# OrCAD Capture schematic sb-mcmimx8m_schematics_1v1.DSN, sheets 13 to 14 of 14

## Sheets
13 12. ALT boot: size C; title: SBC-MCM-iMX8M    12.ALT-BOOT; rev: 2.0
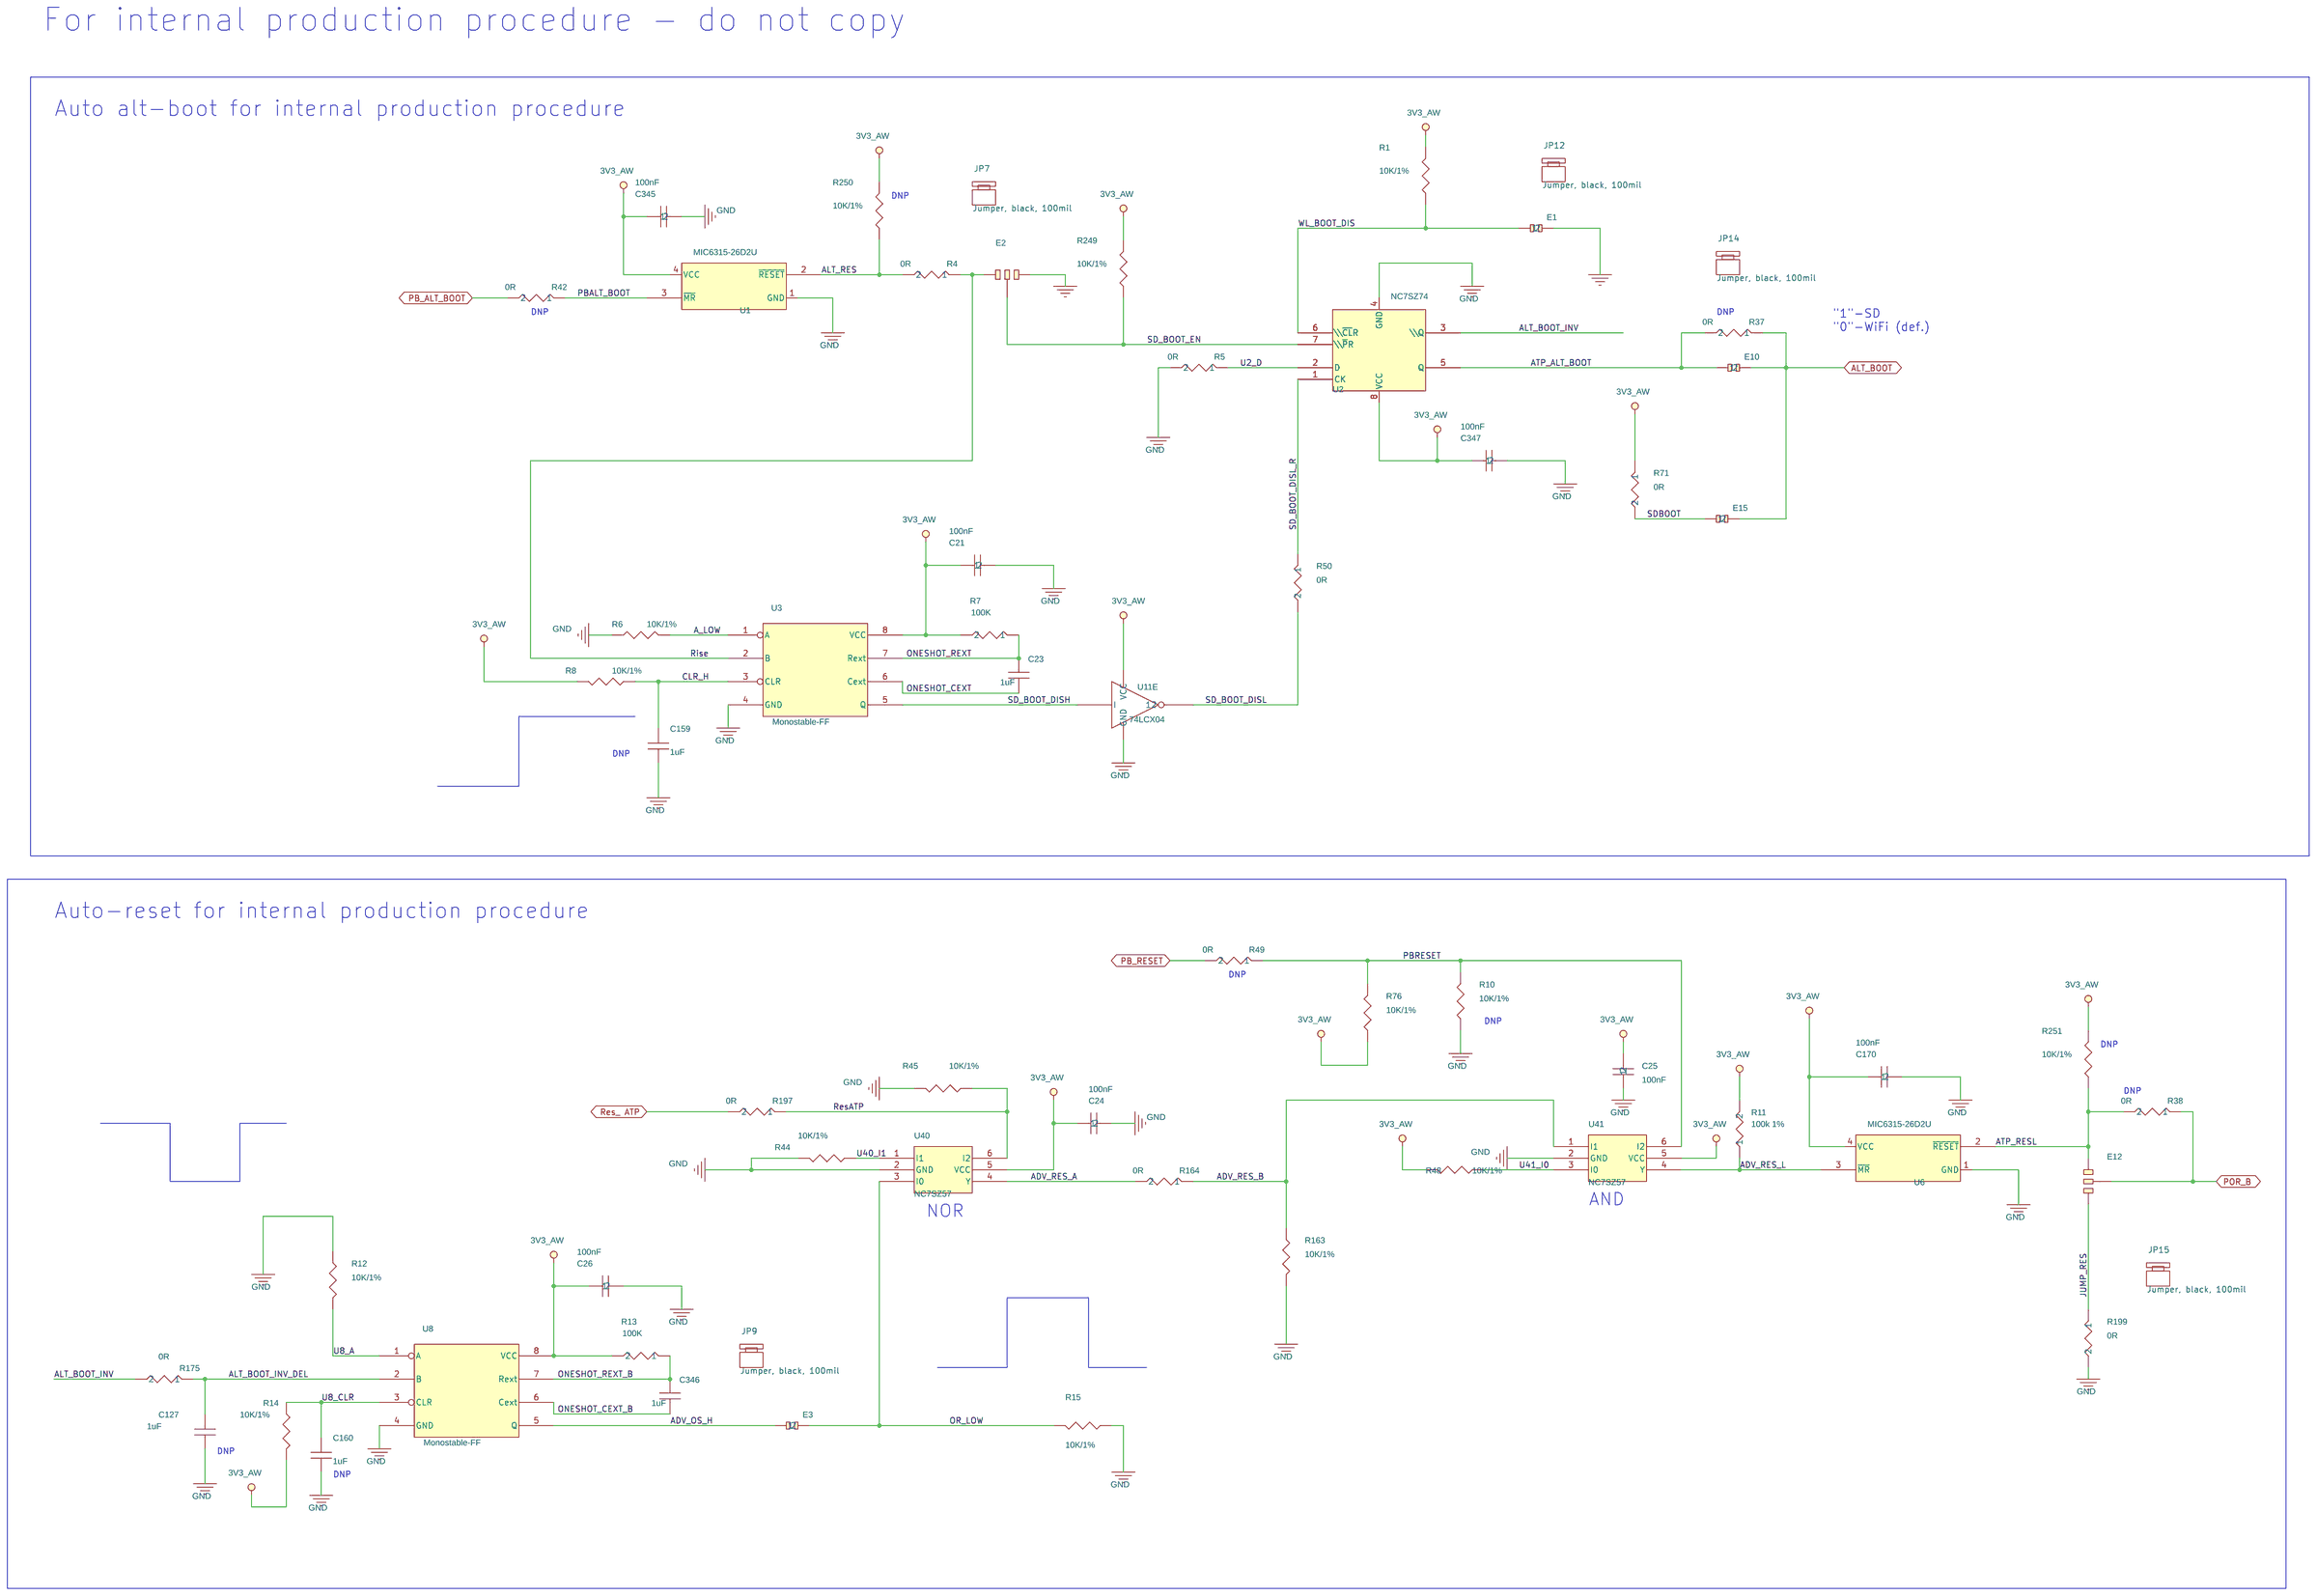
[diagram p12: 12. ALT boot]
14 14. Mechanical,MISC connectors: size B; title: SBC-MCM-iMX8M      11. Mechanical; rev: 2.0
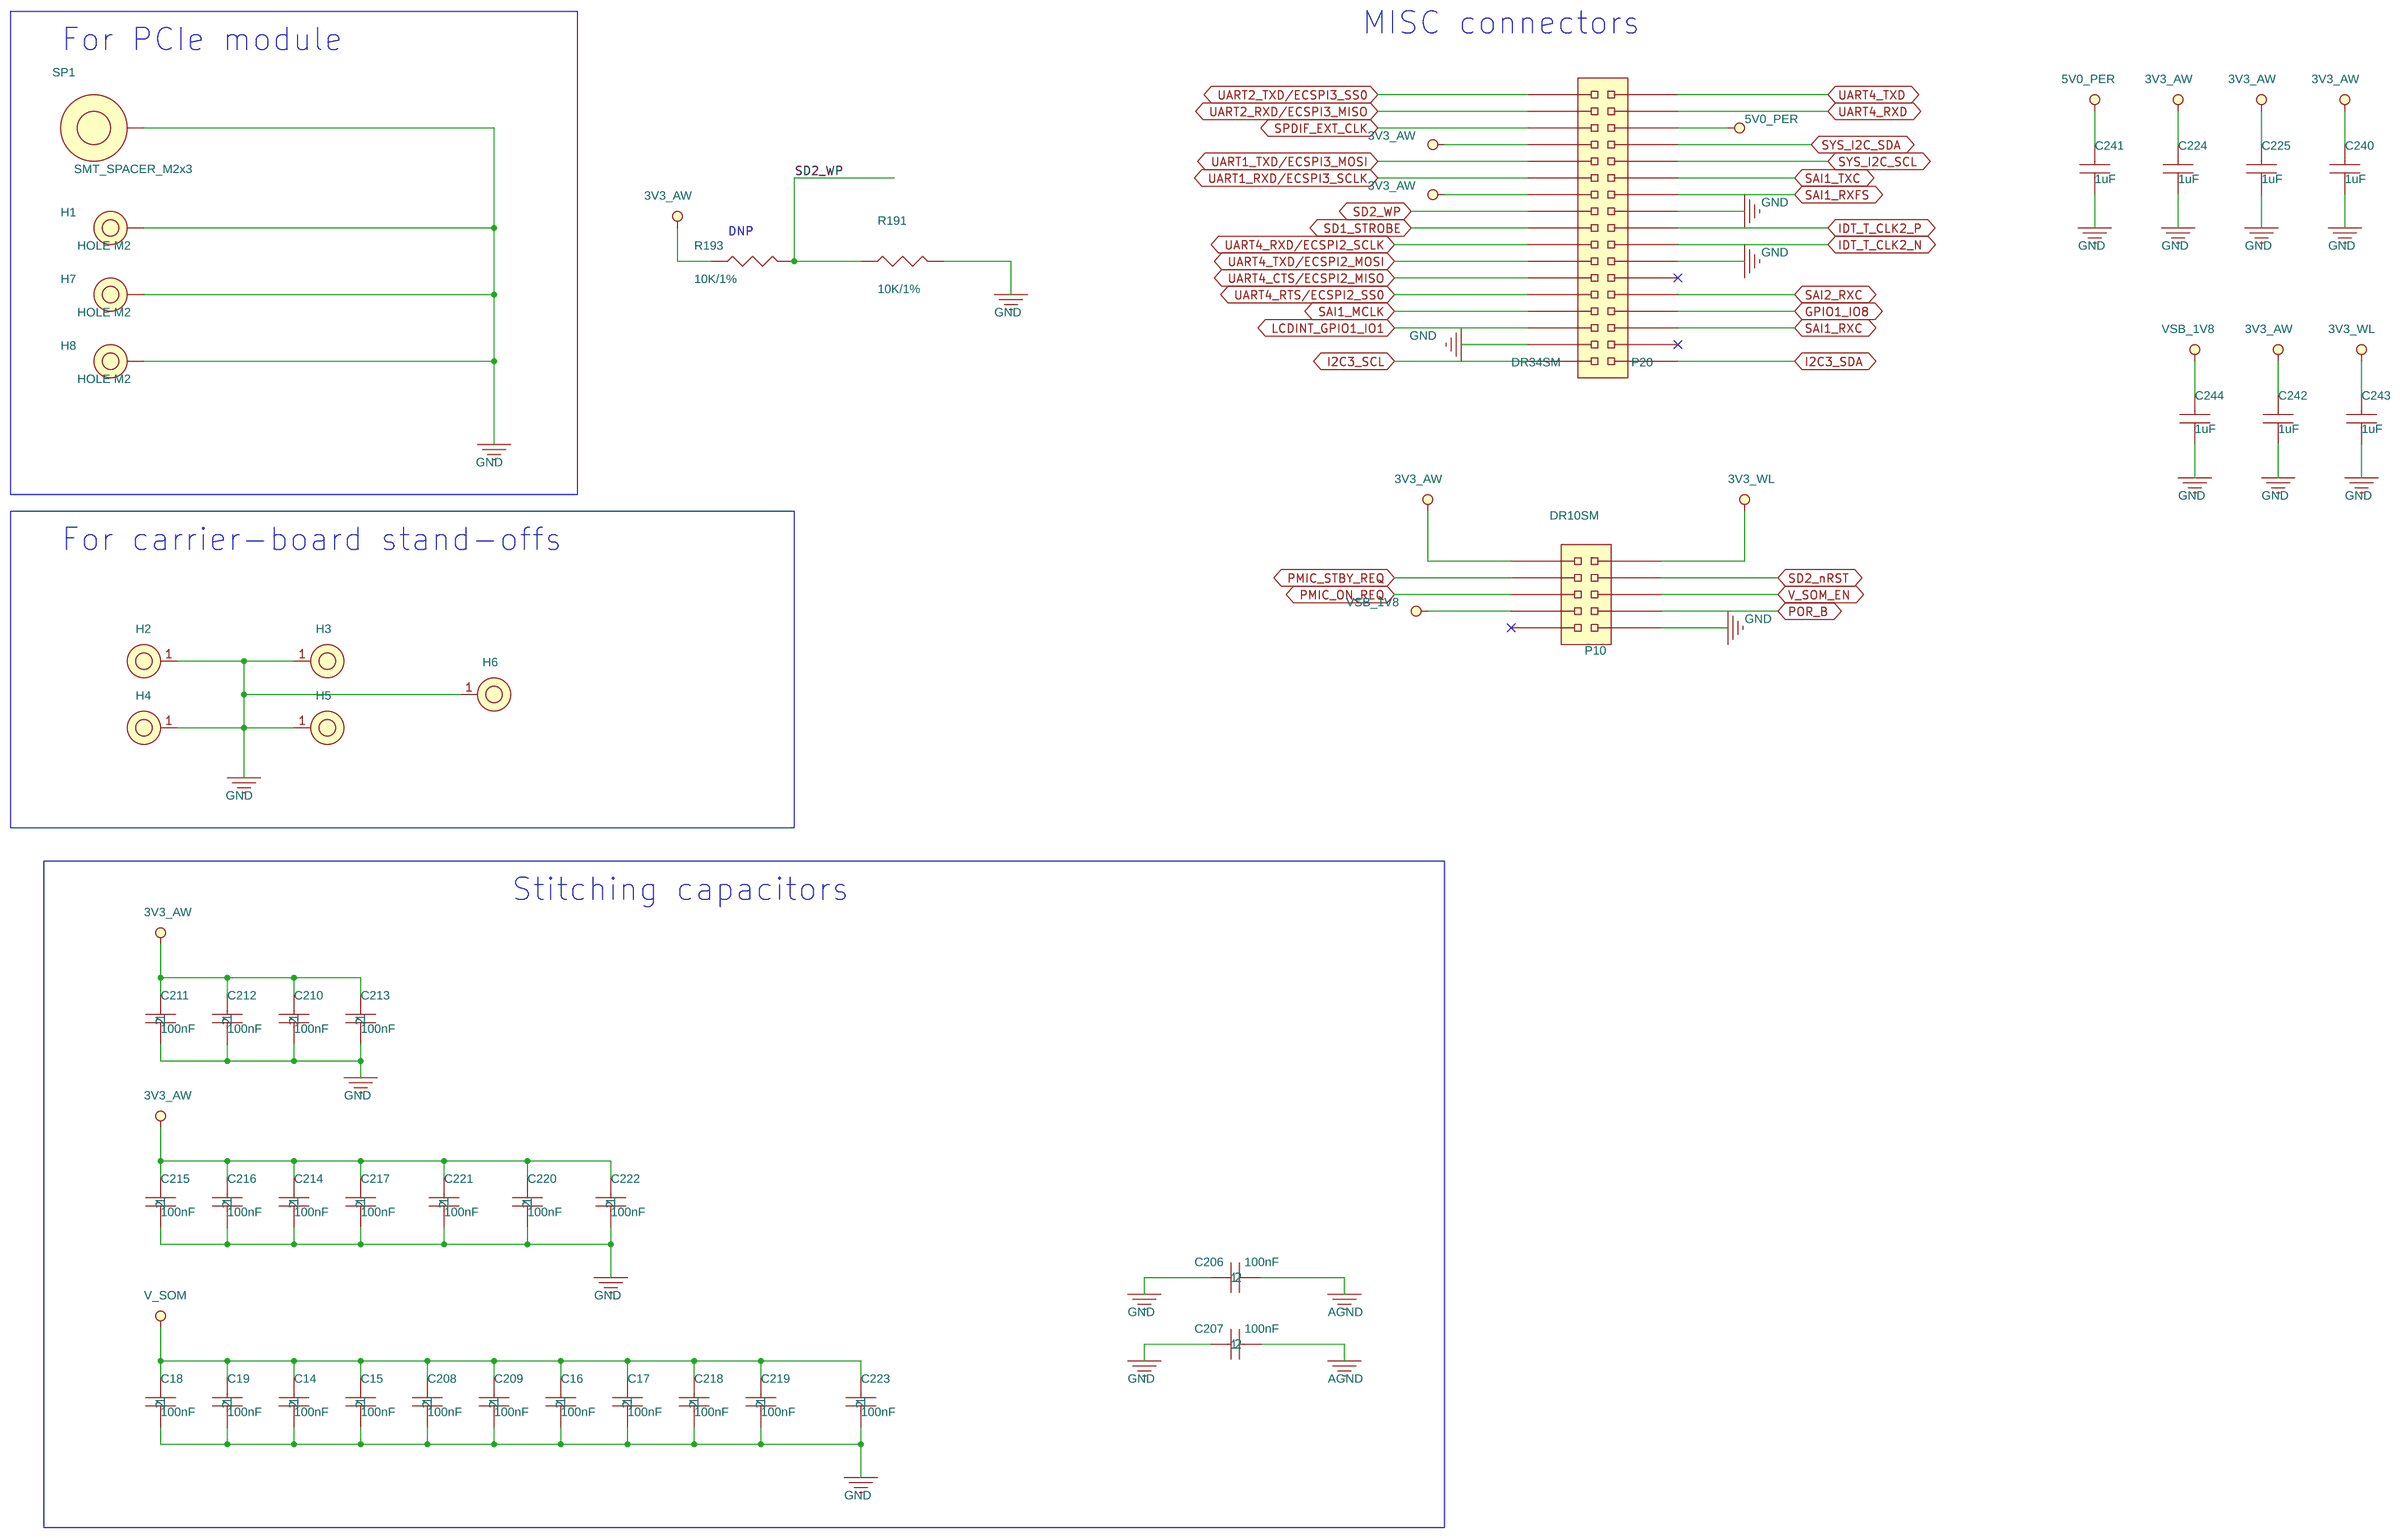
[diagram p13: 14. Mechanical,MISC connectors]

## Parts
sheet 10. UART, RS232, SD, EPROM,QSPI
U11  74LCX04  [TSSOP-14]  (sections A,B,C,D,E,F)
sheet 12. ALT boot
C21  100nF  [RC0402]
C23  1uF  [RC0402]
C24  100nF  [RC0402]
C25  100nF  [RC0402]
C26  100nF  [RC0402]
C127  1uF  [RC0402]
C159  1uF  [RC0402]
C160  1uF  [RC0402]
C170  100nF  [RC0402]
C345  100nF  [RC0402]
C346  1uF  [RC0402]
C347  100nF  [RC0402]
E1  HDR1X2  [1X2THHDR]
E2  JP3  [1X3THHDR]
E3  HDR1X2  [1X2THHDR]
E10  HDR1X2  [1X2THHDR]
E12  JP3  [1X3THHDR]
E15  HDR1X2  [1X2THHDR]
JP7  Jumper, black, 100mil
JP9  Jumper, black, 100mil
JP12  Jumper, black, 100mil
JP14  Jumper, black, 100mil
JP15  Jumper, black, 100mil
R1  10K/1%  [RC0402]
R4  0R  [RC0402]
R5  0R  [RC0402]
R6  10K/1%  [RC0402]
R7  100K  [RC0402]
R8  10K/1%  [RC0402]
R10  10K/1%  [RC0402]
R11  100k 1%  [RC0402]
R12  10K/1%  [RC0402]
R13  100K  [RC0402]
R14  10K/1%  [RC0402]
R15  10K/1%  [RC0402]
R37  0R  [RC0402]
R38  0R  [RC0402]
R42  0R  [RC0402]
R44  10K/1%  [RC0402]
R45  10K/1%  [RC0402]
R48  10K/1%  [RC0402]
R49  0R  [RC0402]
R50  0R  [RC0402]
R71  0R  [RC0402]
R76  10K/1%  [RC0402]
R163  10K/1%  [RC0402]
R164  0R  [RC0402]
R175  0R  [RC0402]
R197  0R  [RC0402]
R199  0R  [RC0402]
R249  10K/1%  [RC0402]
R250  10K/1%  [RC0402]
R251  10K/1%  [RC0402]
U1  MIC6315-26D2U  [SOT-143]
U2  NC7SZ74  [MO-187CA-8]
U3  Monostable-FF  [MO-187CA-8]
U6  MIC6315-26D2U  [SOT-143]
U8  Monostable-FF  [MO-187CA-8]
U40  NC7SZ57  [MO-252UAAD]
U41  NC7SZ57  [MO-252UAAD]
sheet 14. Mechanical,MISC connectors
C14  100nF  [RC0402]
C15  100nF  [RC0402]
C16  100nF  [RC0402]
C17  100nF  [RC0402]
C18  100nF  [RC0402]
C19  100nF  [RC0402]
C206  100nF  [RC0402]
C207  100nF  [RC0402]
C208  100nF  [RC0402]
C209  100nF  [RC0402]
C210  100nF  [RC0402]
C211  100nF  [RC0402]
C212  100nF  [RC0402]
C213  100nF  [RC0402]
C214  100nF  [RC0402]
C215  100nF  [RC0402]
C216  100nF  [RC0402]
C217  100nF  [RC0402]
C218  100nF  [RC0402]
C219  100nF  [RC0402]
C220  100nF  [RC0402]
C221  100nF  [RC0402]
C222  100nF  [RC0402]
C223  100nF  [RC0402]
C224  1uF  [RC0402]
C225  1uF  [RC0402]
C240  1uF  [RC0402]
C241  1uF  [RC0402]
C242  1uF  [RC0402]
C243  1uF  [RC0402]
C244  1uF  [RC0402]
H1  HOLE M2  [M2PAD]
H2  MechHole  [M3PAD]
H3  MechHole  [M3PAD]
H4  MechHole  [M3PAD]
H5  MechHole  [M3PAD]
H6  MechHole  [M3PAD]
H7  HOLE M2  [M2PAD]
H8  HOLE M2  [M2PAD]
P10  DR10SM  [2X5SMHDR]
P20  DR34SM  [2X17SMHDR]
R191  10K/1%  [RC0402]
R193  10K/1%  [RC0402]
SP1  SMT_SPACER_M2x3  [MINIPCIE-4-Spacer]

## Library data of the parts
U11 = 74LCX04_sgl_gate_TSSOP-14: CLABCONF0: =SB-MCM8M
C21 = 100nF,_10V,_X7R,_10%,_0402_4: CLABCONF0: =ATP
C23 C346 = 1uF,X5R,6.3V,0402: CLABCONF0: =ATP
C24 = 100nF,_10V,_X7R,_10%,_0402_6: CLABCONF0: =ATP
C25 = 100nF,_10V,_X7R,_10%,_0402_2: CLABCONF0: =ATP
C26 = 100nF,_10V,_X7R,_10%,_0402_1: CLABCONF0: =ATP
C127 C159 C160 = 1uF,X5R,6.3V,0402: CLABCONF0: DNP
C170 = 100nF,_10V,_X7R,_10%,_0402_5: CLABCONF0: =ATP
C345 = 100nF,_10V,_X7R,_10%,_0402_3: CLABCONF0: =ATP
C347 = 100nF,_10V,_X7R,_10%,_0402: CLABCONF0: =ATP
E1 = HDR_1x2_100MIL_TH_JUMPER_3: CLABCONF0: =ATP
E2 E12 = HDR_1x3_100MIL_TH_JUMPER: CLABCONF0: =ATP
E3 = HDR_1x2_100MIL_TH_JUMPER_1: CLABCONF0: =ATP
E10 = HDR_1x2_100MIL_TH_JUMPER_2: CLABCONF0: =ATP
E15 = HDR_1x2_100MIL_TH_JUMPER: CLABCONF0: =SB-MCM8M
JP7 JP9 JP12 JP14 JP15 = Jumper,_black,_100mil: CLABCONF0: =ATP
R1 = 10K,1%,0402,1_16W_0_9: CLABCONF0: =ATP
R4 = 0R,_0402_0_5: CLABCONF0: =ATP; P/N: 161C00005S
R5 = 0R,_0402_0_7: CLABCONF0: =ATP; P/N: 161C00005S
R6 = 10K,1%,0402,1_16W_0_1: CLABCONF0: =ATP
R7 = 100K,_0402_1: CLABCONF0: =ATP; P/N: 161C10031S
R8 = 10K,1%,0402,1_16W_0_13: CLABCONF0: =ATP
R10 = 10K,1%,0402,1_16W_0_4: CLABCONF0: DNP
R11 = 100k,_%1,_0402: CLABCONF0: =ATP
R12 = 10K,1%,0402,1_16W_0_2: CLABCONF0: =ATP
R13 = 100K,_0402: CLABCONF0: =ATP; P/N: 161C10031S
R14 = 10K,1%,0402,1_16W_0_14: CLABCONF0: =ATP
R15 = 10K,1%,0402,1_16W_0_7: CLABCONF0: =ATP
R37 = 0R,_0402_0_11: CLABCONF0: DNP; P/N: 161C00005S
R38 = 0R,_0402_0: CLABCONF0: DNP; P/N: 161C00005S
R42 = 0R,_0402_0_3: CLABCONF0: DNP; P/N: 161C00005S
R44 = 10K,1%,0402,1_16W_0_6: CLABCONF0: =ATP
R45 = 10K,1%,0402,1_16W_0_3: CLABCONF0: =ATP
R48 = 10K,1%,0402,1_16W_0_12: CLABCONF0: =ATP
R49 = 0R,_0402_0_8: CLABCONF0: DNP; P/N: 161C00005S
R50 = 0R,_0402_0_6: CLABCONF0: =ATP; P/N: 161C00005S
R71 = 0R,_0402_0_4: CLABCONF0: =SB-MCM8M; P/N: 161C00005S
R76 = 10K,1%,0402,1_16W_0_8: CLABCONF0: =ATP
R163 = 10K,1%,0402,1_16W_0_5: CLABCONF0: =ATP
R164 = 0R,_0402_0_9: CLABCONF0: =ATP; P/N: 161C00005S
R175 = 0R,_0402_0_2: CLABCONF0: =ATP; P/N: 161C00005S
R197 = 0R,_0402_0_10: CLABCONF0: =ATP; P/N: 161C00005S
R199 = 0R,_0402_0_1: CLABCONF0: =ATP; P/N: 161C00005S
R249 = 10K,1%,0402,1_16W_0_10: CLABCONF0: =ATP
R250 = 10K,1%,0402,1_16W_0_11: CLABCONF0: DNP
R251 = 10K,1%,0402,1_16W_0: CLABCONF0: DNP
U1 = ADM6315_RESET_1: CLABCONF0: =ATP; P/N: 117A63150S
U2 = NC7SZ74_D-Type_Flip-Flop: CLABCONF0: =ATP; P/N: 106F20740S
U3 U8 = Monostable-FF: CLABCONF0: =ATP; P/N: 106H20000S
U6 = ADM6315_RESET_1: CLABCONF0: =ATP; P/N: 117A63151S
U40 U41 = MicroGate_NC7SZ57,Univ_Gate: CLABCONF0: =ATP; P/N: 106C20570S
C14 = 100nF,_10V,_X7R,_10%,_0402_14: CLABCONF0: =SB-MCM8M; P/N: 151B10400S
C15 = 100nF,_10V,_X7R,_10%,_0402_20: CLABCONF0: =SB-MCM8M; P/N: 151B10400S
C16 = 100nF,_10V,_X7R,_10%,_0402_8: CLABCONF0: =SB-MCM8M; P/N: 151B10400S
C17 = 100nF,_10V,_X7R,_10%,_0402_16: CLABCONF0: =SB-MCM8M; P/N: 151B10400S
C18 = 100nF,_10V,_X7R,_10%,_0402_18: CLABCONF0: =SB-MCM8M; P/N: 151B10400S
C19 = 100nF,_10V,_X7R,_10%,_0402_21: CLABCONF0: =SB-MCM8M; P/N: 151B10400S
C206 = 100nF,_10V,_X7R,_10%,_0402_19: CLABCONF0: =SB-MCM8M; P/N: 151B10400S
C207 = 100nF,_10V,_X7R,_10%,_0402_7: CLABCONF0: =SB-MCM8M; P/N: 151B10400S
C208 = 100nF,_10V,_X7R,_10%,_0402_10: CLABCONF0: =SB-MCM8M; P/N: 151B10400S
C209 = 100nF,_10V,_X7R,_10%,_0402_12: CLABCONF0: =SB-MCM8M; P/N: 151B10400S
C210 = 100nF,_10V,_X7R,_10%,_0402: CLABCONF0: =SB-MCM8M; P/N: 151B10400S
C211 = 100nF,_10V,_X7R,_10%,_0402_1: CLABCONF0: =SB-MCM8M; P/N: 151B10400S
C212 = 100nF,_10V,_X7R,_10%,_0402_4: CLABCONF0: =SB-MCM8M; P/N: 151B10400S
C213 = 100nF,_10V,_X7R,_10%,_0402_6: CLABCONF0: =SB-MCM8M; P/N: 151B10400S
C214 = 100nF,_10V,_X7R,_10%,_0402_9: CLABCONF0: =SB-MCM8M; P/N: 151B10400S
C215 = 100nF,_10V,_X7R,_10%,_0402_11: CLABCONF0: =SB-MCM8M; P/N: 151B10400S
C216 = 100nF,_10V,_X7R,_10%,_0402_15: CLABCONF0: =SB-MCM8M; P/N: 151B10400S
C217 = 100nF,_10V,_X7R,_10%,_0402_17: CLABCONF0: =SB-MCM8M; P/N: 151B10400S
C218 = 100nF,_10V,_X7R,_10%,_0402_23: CLABCONF0: =SB-MCM8M; P/N: 151B10400S
C219 = 100nF,_10V,_X7R,_10%,_0402_3: CLABCONF0: =SB-MCM8M; P/N: 151B10400S
C220 = 100nF,_10V,_X7R,_10%,_0402_2: CLABCONF0: =SB-MCM8M; P/N: 151B10400S
C221 = 100nF,_10V,_X7R,_10%,_0402_5: CLABCONF0: =SB-MCM8M; P/N: 151B10400S
C222 = 100nF,_10V,_X7R,_10%,_0402_22: CLABCONF0: =SB-MCM8M; P/N: 151B10400S
C223 = 100nF,_10V,_X7R,_10%,_0402_13: CLABCONF0: =SB-MCM8M; P/N: 151B10400S
C224 C225 C240-C244 = 1uF,X5R,6.3V,0402: CLABCONF0: =SB-MCM8M
H1 H7 H8 = Hole,_Plated,_M2,_5mm._ext.: CLABCONF0: DNP
H2-H6 = Mechanical_Hole: CLABCONF0: DNP
P10 = HDR_2x5_100MIL_SMT: CLABCONF0: =SB-MCM8M
P20 = HDR_2x17_100MIL_SMT: CLABCONF0: =SB-MCM8M
R191 = 10K,1%,0402,1_16W_0: CLABCONF0: =SB-MCM8M
R193 = 10K,1%,0402,1_16W_0_1: CLABCONF0: DNP
SP1 = SMT_SPACER_M2x3: CLABCONF0: =SB-MCM8M

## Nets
3V3_AW: C21.1 C24.1 C25.2 C26.1 C170.1 C210.1 C211.1 C212.1 C213.1 C214.1 C215.1 C216.1 C217.1 C220.1 C221.1 C222.1 C224.1 C225.1 C240.1 C242.1 C345.1 C347.1 P10.1 P20.7 P20.13 R1.2 R7.2 R8.2 R11.2 R13.2 R14.2 R48.2 R71.1 R76.1 R193.1 R249.2 R250.2 R251.2 U1.4(VCC) U2.8(VCC) U3.8(VCC) U6.4(VCC) U8.8(VCC) U40.5(VCC) U41.5(VCC) ; also on sheet 1 3 4 5 6 7 8 9 10 11 12
3V3_WL: C243.1 P10.2 ; also on sheet 10 12
5V0_PER: C241.1 P20.6 ; also on sheet 1 5 10
AGND: C206.2 C207.2 ; also on sheet 6
GND: C14.2 C15.2 C16.2 C17.2 C18.2 C19.2 C21.2 C24.2 C25.1 C26.2 C127.1 C159.1 C160.1 C170.2 C206.1 C207.1 C208.2 C209.2 C210.2 C211.2 C212.2 C213.2 C214.2 C215.2 C216.2 C217.2 C218.2 C219.2 C220.2 C221.2 C222.2 C223.2 C224.2 C225.2 C240.2 C241.2 C242.2 C243.2 C244.2 C345.2 C347.2 E1.2 E2.3 H1.1 H2.1 H3.1 H4.1 H5.1 H6.1 H7.1 H8.1 P10.10 P20.16 P20.22 P20.31 R5.2 R6.1 R10.1 R12.1 R15.1 R44.2 R45.2 R163.2 R191.2 R199.2 SP1.1 U1.1(GND) U2.4(GND) U3.4(GND) U6.1(GND) U8.4(GND) U40.2(GND) U41.2(GND) ; also on sheet 1 3 4 5 6 7 8 9 10 11 12
A_LOW: R6.2 U3.1(A)
ADV_OS_H: E3.1 U8.5(Q)
ADV_RES_A: R164.2 U40.4(Y)
ADV_RES_B: R163.1 R164.1 U41.1(I1)
ADV_RES_L: R11.1 U6.3(~{MR}) U41.4(Y)
ALT_BOOT: E10.2 E15.2 R37.1 ; also on sheet 3
ALT_BOOT_INV: R175.2 U2.3(\\Q)
ALT_BOOT_INV_DEL: C127.2 R175.1 U8.2(B)
ALT_RES: R4.2 R250.1 U1.2(~{RESET})
ATP_ALT_BOOT: E10.1 R37.2 U2.5(Q)
ATP_RESL: E12.3 R38.2 R251.1 U6.2(~{RESET})
CLR_H: C159.2 R8.1 U3.3(CLR)
GPIO1_IO8: P20.28 ; also on sheet 3
I2C3_SCL: P20.33 ; also on sheet 3
I2C3_SDA: P20.34 ; also on sheet 3
IDT_T_CLK2_N: P20.20 ; also on sheet 9
IDT_T_CLK2_P: P20.18 ; also on sheet 9
JUMP_RES: E12.1 R199.1
LCDINT_GPIO1_IO1: P20.29 ; also on sheet 3 8
ONESHOT_CEXT: C23.2 U3.6(Cext)
ONESHOT_CEXT_B: C346.2 U8.6(Cext)
ONESHOT_REXT: C23.1 R7.1 U3.7(Rext)
ONESHOT_REXT_B: C346.1 R13.1 U8.7(Rext)
OR_LOW: E3.2 R15.2 U40.3(I0)
PB_ALT_BOOT: R42.2 ; also on sheet 3
PB_RESET: R49.2 ; also on sheet 3
PBALT_BOOT: R42.1 U1.3(~{MR})
PBRESET: R10.2 R49.1 R76.2 U41.6(I2)
PMIC_ON_REQ: P10.5 ; also on sheet 3 10
PMIC_STBY_REQ: P10.3 ; also on sheet 3
POR_B: E12.2 P10.8 R38.1 ; also on sheet 3 7 8 9
Res_ ATP: R197.2 ; also on sheet 3
ResATP: R45.1 R197.1 U40.6(I2)
Rise: E2.1 R4.1 U3.2(B)
SAI1_MCLK: P20.27 ; also on sheet 3
SAI1_RXC: P20.30 ; also on sheet 3
SAI1_RXFS: P20.14 ; also on sheet 3
SAI1_TXC: P20.12 ; also on sheet 3
SAI2_RXC: P20.26 ; also on sheet 3
SD1_STROBE: P20.17 ; also on sheet 3
SD2_nRST: P10.4 ; also on sheet 3
SD2_WP: P20.15 R191.1 R193.2 ; also on sheet 3
SD_BOOT_DISH: U3.5(Q) U11.11(I)
SD_BOOT_DISL: R50.2 U11.10(12)
SD_BOOT_DISL_R: R50.1 U2.1(CK)
SD_BOOT_EN: E2.2 R249.1 U2.7(\\~{P}R)
SDBOOT: E15.1 R71.2
SPDIF_EXT_CLK: P20.5 ; also on sheet 3
SYS_I2C_SCL: P20.10 ; also on sheet 3
SYS_I2C_SDA: P20.8 ; also on sheet 3
U2_D: R5.1 U2.2(D)
U8_A: R12.2 U8.1(A)
U8_CLR: C160.2 R14.1 U8.3(CLR)
U40_I1: R44.1 U40.1(I1)
U41_I0: R48.1 U41.3(I0)
UART1_RXD/ECSPI3_SCLK: P20.11 ; also on sheet 3
UART1_TXD/ECSPI3_MOSI: P20.9 ; also on sheet 3
UART2_RXD/ECSPI3_MISO: P20.3 ; also on sheet 3 11
UART2_TXD/ECSPI3_SS0: P20.1 ; also on sheet 3 11
UART4_CTS/ECSPI2_MISO: P20.23 ; also on sheet 3 12
UART4_RTS/ECSPI2_SS0: P20.25 ; also on sheet 3 12
UART4_RXD: P20.4 ; also on sheet 3
UART4_RXD/ECSPI2_SCLK: P20.19 ; also on sheet 3 12
UART4_TXD: P20.2 ; also on sheet 3
UART4_TXD/ECSPI2_MOSI: P20.21 ; also on sheet 3 12
V_SOM: C14.1 C15.1 C16.1 C17.1 C18.1 C19.1 C208.1 C209.1 C218.1 C219.1 C223.1 ; also on sheet 3 8 10
V_SOM_EN: P10.6 ; also on sheet 10
VSB_1V8: C244.1 P10.7 ; also on sheet 7 8 10 12
WL_BOOT_DIS: E1.1 R1.1 U2.6(\\~{CL}R)

Not connected (* = marked no-connect by the designer): P10 9*; P20 24* 32*

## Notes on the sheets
sheet 13
- For internal production procedure - do not copy
- Auto alt-boot for internal production procedure
- DNP
- DNP
- DNP
- "1"-SD
  "0"-WiFi (def.)
- DNP
- Auto-reset for internal production procedure
- DNP
- DNP
- DNP
- DNP
- AND
- NOR
- DNP
- DNP
sheet 14
- MISC connectors
- For PCIe module
- DNP
- For carrier-board stand-offs
- Stitching capacitors
